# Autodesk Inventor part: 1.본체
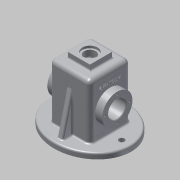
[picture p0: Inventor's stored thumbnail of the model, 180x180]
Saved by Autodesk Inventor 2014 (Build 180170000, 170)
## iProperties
Created: 2017-07
Part Number: 1.본체
Material: 알루미늄 6061
Document SubType Name: Modeling
Designer: 702-09
Density: 2.71 g/cm^3
Appearance: 알루미늄 - 평지
Mass: 940.17 g
Surface Area: 980.418 cm^2
Volume: 346.926 cm^3
Author: 702-09
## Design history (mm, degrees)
sketch "스케치1"
  geometry: 1 further point
sketch "스케치2" dims "d3" = 65, "d4" = 75
  geometry: 2 further points; 1 other entity
  constraints: 1 coincident, 2 other
extrude "돌출1" new body sketch "스케치2" distance "d1" = 10; taper "d2" = 0 deg
sketch "스케치3"
  geometry: L1 (37, -37)-(-37, -37); L2 (-37, -37)-(-37, 37); L3 (-37, 37)-(37, 37); L4 (37, 37)-(37, -37); L5 (37, -37)-(-37, 37); L6 (-37, -37)-(37, 37); 1 further point; 1 other entity
  constraints: 12 end point, 2 midpoint, 2 parallel, 1 horizontal, 1 perpendicular, 1 other
  dimensions: "d5" = 74 distance of L2.end L3.end; "d6" = 74 distance between parallel lines of L1 L3
extrude "돌출2" join sketch "스케치3" distance "d7" = 100; taper "d8" = 0 deg
sketch "스케치4"
  geometry: C1 r 5 at (-58, 0); C2 r 5 at (58, 0); 1 further point; 1 other entity
  constraints: 2 centre point, 1 other
  dimensions: "d9" = 58 distance of point (0, 0) C1.centre; "d10" = 58 distance of C2.centre point (0, 0); "d11" = 10 diameter of C2; "d12" = 10 diameter of C1
extrude "돌출3" cut sketch "스케치4" stored distance "d13" = 100; taper "d14" = 0 deg
sketch "스케치5"
  geometry: L1 (0, 0)-(-100, 0) reference; L2 (18.303, 37)-(-151.464, 37); C1 r 27.5 at (-45, 37); 1 further point
  constraints: 2 end point, 1 centre point, 1 parallel, 1 point on line
  dimensions: "d15" = 55 diameter of C1; "d16" = 55 distance of point (10, 37) C1.centre
extrude "돌출4" join sketch "스케치5" distance "d17" = 13; taper "d18" = 0 deg
sketch "스케치6"
  geometry: L1 (20, -20)-(-20, -20); L2 (-20, -20)-(-20, 20); L3 (-20, 20)-(20, 20); L4 (20, 20)-(20, -20); L5 (20, -20)-(-20, 20); L6 (-20, -20)-(20, 20); 1 further point
  constraints: 12 end point, 2 midpoint, 2 parallel, 1 horizontal, 1 perpendicular
  dimensions: "d19" = 40 distance of L2.end L3.end; "d20" = 40 distance of L1.end L2.end
extrude "돌출5" join sketch "스케치6" distance "d21" = 10; taper "d22" = 0 deg
sketch "스케치8"
  geometry: L1 (0, 0)-(-32, 0); L2 (-32, 105)-(0, 105); L3 (0, 105)-(0, 0); L4 (37, 110)-(37, 10) reference; L5 (37, 10)-(53, 10) reference; L6 (53, 10)-(53, 0) reference; L7 (53, 0)-(-53, 0) reference; L8 (-53, 0)-(-53, 10) reference; L9 (-53, 10)-(-37, 10) reference; L10 (-37, 10)-(-37, 27.5) reference; L11 (-37, 27.5)-(-50, 27.5) reference; L12 (-50, 27.5)-(-50, 82.5) reference; L13 (-50, 82.5)-(-37, 82.5) reference; L14 (-37, 82.5)-(-37, 110) reference; L15 (-37, 110)-(-20, 110) reference; L16 (-20, 110)-(-20, 120) reference; L17 (-20, 120)-(20, 120) reference; L18 (20, 120)-(20, 110) reference; L19 (20, 110)-(37, 110) reference; L20 (-75, 0)-(-75, 10) reference; L21 (-75, 10)-(-63, 10) reference; L22 (-63, 10)-(-63, 0) reference; L23 (-63, 0)-(-75, 0) reference; L24 (75, 10)-(75, 0) reference; L25 (75, 0)-(63, 0) reference; L26 (63, 0)-(63, 10) reference; L27 (63, 10)-(75, 10) reference; L28 (-25, 34.707)-(-25, 75.293); L29 (-25.146, 75.646)-(-31.854, 82.354); L30 (-32, 82.707)-(-32, 105); L31 (-31.854, 27.646)-(-25.146, 34.354); L32 (-32, 0)-(-32, 27.293); L33 (32, 105)-(0, 105); L34 (32, 82.707)-(32, 105); L35 (25.146, 75.646)-(31.854, 82.354); L36 (25, 34.707)-(25, 75.293); L37 (31.854, 27.646)-(25.146, 34.354); L38 (32, 0)-(32, 27.293); L39 (0, 0)-(32, 0); A1 r 0.5 centre (25.5, 75.293) between (25.146, 75.646) and (25, 75.293); A2 r 0.5 centre (31.5, 82.707) between (31.854, 82.354) and (32, 82.707); A3 r 0.5 centre (25.5, 34.707) between (25, 34.707) and (25.146, 34.354); A4 r 0.5 centre (31.5, 27.293) between (32, 27.293) and (31.854, 27.646); A5 r 0.5 centre (-31.5, 27.293) between (-31.854, 27.646) and (-32, 27.293); A6 r 0.5 centre (-25.5, 34.707) between (-25.146, 34.354) and (-25, 34.707); A7 r 0.5 centre (-25.5, 75.293) between (-25, 75.293) and (-25.146, 75.646); A8 r 0.5 centre (-31.5, 82.707) between (-32, 82.707) and (-31.854, 82.354); 8 further points
  constraints: 30 end point, 16 point on circle, 16 point on line, 16 tangent, 8 centre point, 7 equal radius, 6 symmetric about line, 2 parallel, 1 horizontal, 1 perpendicular
  dimensions: "d23" = 32 distance of L1.start L1.end; "d24" = 135 deg angle of L30 L29; "d26" = 135 deg angle of L32 L31; "d27" = 7 distance from line of point (-25, 34.5) L32; "d28" = 7 distance from line of point (-25, 75.5) L30; "d29" = 5 distance between parallel lines of L2 L15; "d70" = 0.5 radius of A1
extrude "돌출6" cut sketch "스케치8" stored distance "d30" = 64; taper "d31" = 0 deg
sketch "스케치9" dims "d32" = 45
  geometry: C1 r 27.5 at (0, 0) reference; 3 further points
  constraints: 1 coincident, 1 horizontal alignment, 2 other
hole "구멍1" sketch "스케치9" at (-22.5, 0) diameter "d33" = 3.242; stored, may be unused: countersink angle "d37" = 90 deg, drill point angle "d39" = 118 deg; dims "d34" = 8, "d35" = 4, "d36" = 2, "d38" = 10
hole "구멍2" diameter "d45" = 32; stored, may be unused: countersink angle "d49" = 90 deg, drill point angle "d51" = 0 deg; dims "d43" = 10, "d44" = 10, "d46" = 45, "d47" = 4, "d48" = 2, "d50" = 10
sketch "스케치10"
  geometry: 2 further points
  constraints: 1 coincident
hole "구멍3" sketch "스케치10" at (0, 0) diameter "d52" = 21; stored, may be unused: countersink angle "d56" = 90 deg, drill point angle "d58" = 0 deg; dims "d53" = 45, "d54" = 28, "d55" = 4, "d57" = 10
sketch "스케치11"
  geometry: L1 (65, 10)-(65, 0) reference; L2 (65, 0)-(32, 0) reference; L3 (32, 0)-(32, 105) reference; L4 (32, 105)-(10.5, 105) reference; L5 (10.5, 105)-(10.5, 116) reference; L6 (10.5, 116)-(14, 116) reference; L7 (14, 116)-(14, 120) reference; L8 (14, 120)-(20, 120) reference; L9 (20, 120)-(20, 110) reference; L10 (20, 110)-(37, 110) reference; L11 (37, 110)-(37, 10) reference; L12 (37, 10)-(65, 10) reference; L13 (-65, 0)-(-65, 10) reference; L14 (-65, 10)-(-37, 10) reference; L15 (-37, 10)-(-37, 110) reference; L16 (-37, 110)-(-20, 110) reference; L17 (-20, 110)-(-20, 120) reference; L18 (-20, 120)-(-14, 120) reference; L19 (-14, 120)-(-14, 116) reference; L20 (-14, 116)-(-10.5, 116) reference; L21 (-10.5, 116)-(-10.5, 105) reference; L22 (-10.5, 105)-(-32, 105) reference; L23 (-32, 105)-(-32, 0) reference; L24 (-32, 0)-(-65, 0) reference; L25 (55, 10)-(37, 82.194); 1 further point
  constraints: 2 end point, 2 point on line
  dimensions: "d59" = 10 distance from line of L1 L25.start; "d60" = 14 deg angle of L25 L1
feature "리브1" sketch "스케치11" dims "d61" = 1, "d62" = 10, "d63" = 0, "d64" = 0, "d65" = 1, "d66" = 1
fillet "모깎기1" dims "d67" = 8
fillet "모깎기2" dims "d68" = 8
fillet "모깎기3" dims "d69" = 3
fillet "모깎기4" dims "d71" = 3
chamfer "모따기1" distance "d72" = 1; stored, may be unused: second distance "d73" = 2, angle "d74" = 45 deg
sketch "스케치12"
  geometry: L1 (89, 66)-(0, 66) reference; L2 (-18, 9)-(-18, 49) reference; 2 further points
  constraints: 1 other
  dimensions: "d75" = 37 distance from line of L1 point (12, 29); "d76" = 30 distance from line of point (12, 29) L2
feature "엠보싱1" sketch "스케치12" dims "d77" = 0.5, "d78" = 0
node "솔리드1"
pattern_circular "원형 패턴1" dims angle "d41" = 360 deg
mirror "대칭1"
mirror "대칭2"
node "절단 모서리 투영1"
node "절단 모서리 투영2"
